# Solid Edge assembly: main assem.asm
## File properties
Author: Deepak Maini
Template: Normal.asm
Last saved by: CADCIM
Revision: 12
Application: Solid Edge
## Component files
master rod.par
piston.par
piston pin.par
arti subassm.asm
piston pin plug.par
piston ring.par
master rod bearing.par
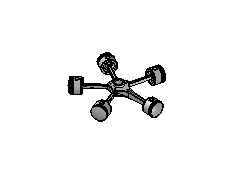
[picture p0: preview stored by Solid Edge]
